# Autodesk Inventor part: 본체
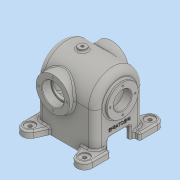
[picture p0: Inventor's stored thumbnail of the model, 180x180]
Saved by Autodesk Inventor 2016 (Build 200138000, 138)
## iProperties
Created: 2024-09
Part Number: 본체
Material: 일반
Document SubType Name: Modeling
Designer: pc-7
Density: 1 g/cm^3
Appearance: 기본값
Author: pc-7
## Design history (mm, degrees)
sketch "스케치1"
  geometry: L1 (-45, 76)-(45, 76); L2 (45, 76)-(45, 0); L3 (45, 0)-(-45, 0); L4 (-45, 0)-(-45, 76); A1 r 45 centre (0, 76) between (45, 76) and (-45, 76); 2 further points
  constraints: 8 end point, 2 midpoint, 2 parallel, 2 point on circle, 1 centre point, 1 coincident, 1 horizontal, 1 perpendicular
  dimensions: "d0" = 90 distance between parallel lines of L2 L4; "d1" = 76 distance between parallel lines of L3 L1
extrude "돌출1" new body sketch "스케치1" stored distance "d2" = 108; taper "d3" = 0 deg
sketch "스케치2"
  geometry: L1 (-45, 0)-(45, 0) reference; C1 r 28.5 at (0, 76); 2 further points
  constraints: 1 centre point, 1 midpoint, 1 vertical alignment
  dimensions: "d4" = 57 diameter of C1; "d5" = 76 distance of point (0, 0) C1.centre
extrude "돌출2" join sketch "스케치2" distance "d6" = 6; taper "d7" = 0 deg
sketch "스케치3"
  geometry: L1 (104.5, 60)-(47.5, 60) reference; C1 r 31 at (76, -14); 1 further point
  constraints: 1 centre point
  dimensions: "d8" = 76 horizontal distance of point (0, 0) C1.centre; "d9" = 62 diameter of C1; "d10" = 74 distance from line of L1 C1.centre
extrude "돌출3" join sketch "스케치3" stored distance "d11" = 108; taper "d12" = 0 deg
sketch "스케치4"
  geometry: L1 (104.5, 60)-(47.5, 60) reference; L2 (76, 60)-(76, -45); L3 (76, -45)-(112, -45); L4 (112, -45)-(112, 45); L5 (112, 45)-(92.5, 45); L6 (92.5, 45)-(92.5, 60); L7 (92.5, 60)-(76, 60); L8 (76, -54)-(121, -54) reference; L9 (121, 54)-(76, 54) reference; 2 further points
  constraints: 12 end point, 4 perpendicular, 1 collinear, 1 midpoint, 1 point on line, 1 vertical
  dimensions: "d18" = 9 distance between parallel lines of L8 L3; "d19" = 9 distance between parallel lines of L9 L5; "d20" = 33 diameter of L6 L2; "d21" = 72 diameter of L4 L2
revolve "회전1" sketch "스케치4" stored, may be unused: angle "d22" = 90 deg
sketch "스케치5"
  geometry: 1 further point
sketch "스케치6"
  geometry: L1 (74, -28.5)-(74, 28.5) reference; 2 further points
  dimensions: "d23" = 76 vertical distance of point (14, -76) point (0, 0); "d24" = 74 distance from line of L1 point (0, 0)
hole "구멍1" sketch "스케치6" at (0, 0) diameter "d25" = 35; stored, may be unused: countersink angle "d29" = 82 deg, drill point angle "d31" = 0 deg; dims "d26" = 6, "d27" = 40, "d28" = 16, "d30" = 25
sketch "스케치7"
  geometry: L1 (-20, 23)-(20, 23); L2 (20, 23)-(20, 0); L3 (20, 0)-(-20, 0); L4 (-20, 0)-(-20, 23); L5 (-45, 0)-(45, 0) reference; 2 further points
  constraints: 8 end point, 2 midpoint, 2 parallel, 1 horizontal, 1 perpendicular
  dimensions: "d32" = 23 distance between parallel lines of L3 L1; "d33" = 40 distance between parallel lines of L2 L4
extrude "돌출4" cut sketch "스케치7" distance "d34" = 108; taper "d35" = 0 deg
sketch "스케치8"
  geometry: L1 (-36, 0)-(-36, 49); L2 (45, 0)-(20, 0) reference; L3 (-45, 0)-(-45, 76) reference; L4 (45, 76)-(45, 0) reference; L5 (-20, 0)-(-45, 0) reference; L6 (20, 23)-(-20, 23) reference; L7 (-20, 23)-(-20, 0) reference; L8 (20, 0)-(20, 23) reference; L9 (36, 0)-(36, 49); L10 (36, 0)-(20, 0); L11 (20, 0)-(20, 23); L12 (20, 23)-(-20, 23); L13 (-20, 23)-(-20, 0); L14 (-36, 0)-(-20, 0); C1 r 36 at (0, 76) reference; A1 r 45 centre (0, 76) between (-36, 49) and (36, 49); 1 further point
  constraints: 15 end point, 5 collinear, 2 point on circle, 2 vertical, 1 centre point, 1 coincident, 1 point on line
  dimensions: "d37" = 9 distance between parallel lines of L3 L1; "d39" = 9 distance between parallel lines of L4 L9; "d40" = 45 radius of A1
extrude "돌출5" cut sketch "스케치8" stored distance "d41" = 91; taper "d42" = 0 deg
node "작업 평면1"
sketch "스케치9"
  geometry: L1 (28.5, 60)-(-28.5, 60) reference; C1 r 7.5 at (0, -14); 1 further point
  constraints: 1 centre point, 1 vertical alignment
  dimensions: "d44" = 74 distance from line of L1 C1.centre; "d45" = 15 diameter of C1
extrude "돌출6" join sketch "스케치9" stored distance "d46" = 91; taper "d47" = 0 deg
node "작업 평면3"
  node "작업 평면2"
sketch "스케치10"
  geometry: L1 (7.5, -28.5)-(7.5, 28.5) reference; C1 r 7.5 at (-66.5, 0); 1 further point
  constraints: 1 centre point, 1 horizontal alignment, 1 midpoint
  dimensions: "d52" = 74 distance from line of L1 C1.centre; "d53" = 15 diameter of C1
extrude "돌출7" join sketch "스케치10" stored distance "d54" = 91; taper "d55" = 0 deg
sketch "스케치11"
  geometry: C1 r 7.5 at (0, 0) reference; 2 further points
  constraints: 1 coincident
hole "구멍2" sketch "스케치11" at (0, 0) diameter "d56" = 4.917; stored, may be unused: countersink angle "d60" = 82 deg, drill point angle "d62" = 0 deg; dims "d57" = 12, "d58" = 40, "d59" = 16, "d61" = 17.1
sketch "스케치12"
  geometry: C1 r 7.5 at (0, 0) reference; C2 r 2.458 at (0, 0) reference; 2 further points
  constraints: 1 coincident
hole "구멍3" sketch "스케치12" at (0, 0) diameter "d63" = 4.917; stored, may be unused: countersink angle "d67" = 82 deg, drill point angle "d69" = 0 deg; dims "d64" = 12, "d65" = 40, "d66" = 16, "d68" = 17.1
sketch "스케치13" dims "d70" = 52
  geometry: C1 r 31 at (0, 0) reference; 3 further points
  constraints: 2 vertical alignment, 1 coincident, 2 other
hole "구멍4" sketch "스케치13" at (0, 26) diameter "d71" = 3.242; stored, may be unused: countersink angle "d75" = 82 deg, drill point angle "d77" = 118 deg; dims "d72" = 8, "d73" = 40, "d74" = 16, "d76" = 10
sketch "스케치14" dims "d81" = 46
  geometry: C1 r 28.5 at (0, 0) reference; C2 r 28.5 at (0, 0) reference; 3 further points
  constraints: 2 vertical alignment, 1 coincident, 2 other
hole "구멍5" sketch "스케치14" at (0, 23) diameter "d82" = 3.242; stored, may be unused: countersink angle "d86" = 82 deg, drill point angle "d88" = 118 deg; dims "d83" = 8, "d84" = 40, "d85" = 16, "d87" = 10
sketch "스케치15"
  geometry: L1 (18, 0)-(18, -10); L2 (18, -10)-(-15, -10); L3 (-15, -10)-(-15, 0); L4 (0, 0)-(0, 108) reference; L5 (0, 26)-(-20.693, 16.79); L6 (25, 0)-(0, 0) reference; L7 (18, 0)-(0, 0); L8 (0, 26)-(0, 0); A1 r 14 centre (-15, 4) between (-20.693, 16.79) and (-15, -10); 1 further point
  constraints: 12 end point, 3 perpendicular, 3 point on line, 2 point on circle, 1 centre point, 1 collinear, 1 tangent, 1 vertical
  dimensions: "d92" = 18 distance between parallel lines of L1 L4; "d94" = 60 distance from line of point (45, 54) L3; "d95" = 36 distance from line of L5.start L2; "d96" = 10 distance between parallel lines of L6 L2; "d97" = 14 distance from line of A1.centre L2
extrude "돌출8" join sketch "스케치15" distance "d98" = 12; taper "d99" = 0 deg
sketch "스케치16"
  geometry: 2 further points
  dimensions: "d100" = 50 vertical distance of point (45, -54) point (-15, -4); "d101" = 60 horizontal distance of point (-15, -4) point (45, -54)
hole "구멍6" sketch "스케치16" at (-15, -4) diameter "d102" = 6.6; stored, may be unused: countersink angle "d106" = 82 deg, drill point angle "d108" = 0 deg; dims "d103" = 8, "d104" = 18, "d105" = 2, "d107" = 10
fillet "모깎기1" dims "d115" = 12
fillet "모깎기2" dims "d116" = 3
fillet "모깎기3" dims "d117" = 3
fillet "모깎기4" dims "d118" = 3
fillet "모깎기5" dims "d119" = 3
fillet "모깎기6" dims "d120" = 3
fillet "모깎기7" dims "d121" = 3
fillet "모깎기8" dims "d122" = 3
fillet "모깎기9" dims "d123" = 3
fillet "모깎기10" dims "d124" = 3
fillet "모깎기11" dims "d125" = 3
fillet "모깎기12" dims "d126" = 3
fillet "모깎기13" dims "d127" = 3
fillet "모깎기14" dims "d128" = 3
fillet "모깎기15" dims "d129" = 3
fillet "모깎기16" dims "d130" = 3
fillet "모깎기17" dims "d131" = 3
fillet "모깎기18" dims "d132" = 3
sketch "스케치17"
  geometry: L1 (-20.739, 38.002)-(20.739, 38.002); L2 (20.739, 38.002)-(20.739, 31.998); L3 (20.739, 31.998)-(-20.739, 31.998); L4 (-20.739, 31.998)-(-20.739, 38.002); L5 (-20.739, 35)-(20.739, 35); L6 (0, 38.002)-(0, 31.998); 2 further points
  constraints: 5 midpoint, 4 end point, 1 vertical alignment, 2 other
  dimensions: "d133" = 35 distance from line of point (0, 0) L5
feature "엠보싱1" sketch "스케치17" dims "d134" = 0.5, "d135" = 0
chamfer "모따기1" distance "d136" = 1; stored, may be unused: second distance "d137" = 2, angle "d138" = 45 deg
chamfer "모따기2" distance "d139" = 1; stored, may be unused: second distance "d140" = 2, angle "d141" = 45 deg
chamfer "모따기3" distance "d142" = 1; stored, may be unused: second distance "d143" = 2, angle "d144" = 45 deg
fillet "모깎기19" dims "d145" = 0.3
fillet "모깎기20" dims "d146" = 3
node "솔리드1"
mirror "대칭1"
pattern_circular "원형 패턴1" dims angle "d79" = 360 deg
mirror "대칭2"
pattern_circular "원형 패턴2" dims angle "d90" = 360 deg
mirror "대칭3"
mirror "대칭4"
pattern_linear "직사각형 패턴1" dims "d111" = 100
node "작업축1"
other parameters: "d43" = 125, "d48" = 0, "d49" = -49
